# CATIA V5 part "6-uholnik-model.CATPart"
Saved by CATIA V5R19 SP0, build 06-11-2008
Part number: 6 uholnik
Bounding box of the stored display mesh (mm): x -26.642 to 26.642, y -30.139 to 30.139, z 0 to 7.313
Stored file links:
  G:\Dokumenty od 01.06.2010\CATIA V5 R19 dokumenty\Lopta\6-uholnik-model.CATPart
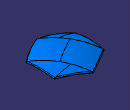
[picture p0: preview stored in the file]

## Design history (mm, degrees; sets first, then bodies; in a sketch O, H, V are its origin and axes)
AxisSystem1: origin (0, 0, 0), X (1, 0, 0), Y (0, 1, 0), Z (0, 0, 1)
AxisSystem2: origin (0, 0, -68.0185), X (0.866, 0.5, 0), Y (-0.4671, 0.809, 0.3568), Z (0.1784, -0.309, 0.9342)
Circle1: type CtrPt, Start 0, End -30, Support Fill1, Center Point2, RefPoint vertex [face of Line5 | face of Line3]
Line1: type PtPt, Start 1, SecondPoint Point2, FirstPoint vertex [face of Line7 | face of Line4]
Fill1: Boundary (Join1; Line8; Line9; Line10)
Body1 (main body)
  DatumPoint1 to DatumPoint4
  Line2: type PtPt, SecondPoint DatumPoint4, FirstPoint DatumPoint3
  DatumCurve1
  Line3: type PtDir, Direction DatumCurve1, Start 0, End 60, RefPoint vertex of Line2
  DatumPoint5
  DatumCurve2
  Line4: type PtDir, Direction DatumCurve2, Start 0, End 60, RefPoint DatumPoint5
  DatumCurve3
  Line5: type PtDir, Direction DatumCurve3, Start 0, End 15, RefPoint vertex of Line2
  Line6: type PtDir, Direction Line2, Start 0, End 150, RefPoint vertex of Line5
  Line7: type PtPt, SecondPoint vertex of Line5, FirstPoint vertex of Line4
  Line8: type PtDir, Direction Line6, Start 0, End 145.623, RefPoint vertex of Line3
  Line9: type PtDir, Direction Line3, Start 0, End 150, RefPoint vertex of Line8
  Line10: type PtPt, SecondPoint vertex of Line4, FirstPoint vertex of Line9
  Join1: Elements (Line4; Line7; Line5; Line3)
  Point1: type OnCurve, Support Line8, Length 72.8115
  Line11: type PtDir, Direction Join1, Start 0, End 150, RefPoint Point1
  Line12: type PtDir, Direction Line8, Start 0, End 145.623, RefPoint vertex [face of Line5 | face of Line7]
  Point2: type OnCurve, Support Line11, Length 75
  DatumPoint6
  Line13: type PtPt, SecondPoint DatumPoint6, FirstPoint Point2
  DatumPoint7
  Line14: type PtPt, SecondPoint DatumPoint7, FirstPoint Point2
  Line15: type PtPt, SecondPoint vertex of Line14, FirstPoint vertex of Line13
  Line16: type PtDir, Direction Join1, Start 0, End 75, RefPoint Point2
  Plane1: type 3Points, Element1 Point2, Element2 vertex of Line16, Element3 vertex of Line13
  Line17: type PtDir, Direction Line16, Start 0, End 75, RefPoint Point2
  Line18: type PtDir, Direction Line13, Start 0, End 100, RefPoint Point1
  Line19: type PtDir, Direction Join1, Start 0, End 150, RefPoint vertex of Line18
  Line20: type PtPt, SecondPoint vertex of Line17, FirstPoint vertex of Line19
  Fill2: Boundary (Line16; Line17; Line20; Line19; Line18)
  Line21: type PtPt, Start 1, SecondPoint Point2, FirstPoint vertex [face of Line3 | face of Line5]
  Plane2: type Offset, Offset 0, RefPlane XY plane of AxisSystem2
  Plane3: type OffsetPt, RefPlane YZ plane of AxisSystem2, RefPoint Point2
  Plane4: type OffsetPt, RefPlane ZX plane of AxisSystem2, RefPoint Point2
  Circle2: type 2PointsRad, Start 0, End 336, Support Plane4, SecondPoint vertex of Line21, Radius 75.341, FirstPoint vertex of Line1
  Trim1: Trimmed (Circle1; Line1)
  Line22: type PtPt, SecondPoint vertex of Circle2, FirstPoint vertex [face of Line7 | face of Line4]
  Trim2: Trimmed (Trim1; Line22)
  Trim3: Trimmed (Trim2; Line21)
  Fill3: Boundary (Circle2; Trim3)
  Boundary1: Boundary Fill3
  Line23: type PtPt, SecondPoint vertex [face of Line3 | face of Line5], FirstPoint vertex of Line15
  Line24: type PtPt, SecondPoint vertex [face of Line7 | face of Line4], FirstPoint vertex of Line15
  Line25: type PtPt, SecondPoint vertex [face of Line3 | face of Line5], FirstPoint vertex of Line15
  Line26: type PtPt, SecondPoint vertex of Line15, FirstPoint vertex [face of Line7 | face of Line4]
  Point3: type OnCurve, Support Line26, Length 30
  Line27: type PtPt, SecondPoint Point2, FirstPoint Point3
  Line28: type PtDir, Direction Line12, Start 0, End 75.341, RefPoint Point2
  Line29: type PtDir, Direction Line27, Start 0, End 75.341, RefPoint Point2
  Circle3: type 2PointsRad, Start 0, End -30, Support Plane3, SecondPoint vertex of Line29, Radius 75.341, FirstPoint vertex of Line28
  Rib1: profile Boundary1, centre curve Circle3
  CircPattern1: of the body so far, instances 6, angular step 60, axis from Line29
  Fillet1: radius 0.8, on edge [face of CircPattern1 | face of CircPattern1] (x5); edge [face of Rib1 | face of Rib1]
